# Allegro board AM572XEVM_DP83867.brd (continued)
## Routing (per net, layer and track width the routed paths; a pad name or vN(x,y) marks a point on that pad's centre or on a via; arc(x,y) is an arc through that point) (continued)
ETH1_TRD[1]N: length 43.3
  TOP w0.102: v3(105.76,71.06) 105.76,71.32 105.83,71.4 105.83,73.79 105.76,73.87 U49.6 105.79,74.31 105.79,75.09 U49.5 105.76,75.5 105.69,75.56 v1(105.69,75.84)
  TOP w0.12: v3(105.76,71.06) 105.76,70.29 U15.5
  INT_L3 w0.094: P5.5 98.32,94.16 98.12,93.96 98.12,92.16 97.48,91.52 94.76,91.52 93.78,90.54 93.78,88.05 95.48,86.36 106.73,86.36 108.57,84.52 108.57,79.81 105.81,77.05 105.81,76.33 105.69,76.21 v1(105.69,75.84)
  BOTTOM w0.102: v3(105.76,71.06) 105.77,71.05 C538.2
ETH1_TRD[1]P: length 43.2
  TOP w0.102: v1(106.32,75.84) 106.32,75.56 106.26,75.5 U49.4 106.22,75.09 106.22,74.31 U49.7 106.27,74.27 106.27,73.86 106.19,73.78 106.19,71.4 106.27,71.33 v3(106.27,71.06)
  TOP w0.12: v3(106.27,71.06) 106.27,70.3 U15.4
  INT_L3 w0.094: v1(106.32,75.84) 106.32,76.21 106.2,76.33 106.2,76.89 108.97,79.65 108.97,84.68 106.89,86.76 95.64,86.76 94.18,88.22 94.18,90.37 94.93,91.12 97.65,91.12 98.52,91.99 98.52,93.79 98.65,93.93 99.14,93.93 99.33,93.74 P5.11
  BOTTOM w0.102: v3(106.27,71.06) 106.27,71.05 C539.2
ETH1_TRD[2]N: length 44.1
  TOP w0.102: P5.10 101.35,92.98 101.35,94.03 101.55,94.23 101.76,94.23 102.16,93.83 102.16,92.04 101.63,91.52 96.75,91.52 95.73,90.5 95.73,88.45 97.64,86.54 106.53,86.54 107.65,85.42 107.65,78.33 106.43,77.11 105.13,77.11 104.33,76.32 104.33,75.65 104.26,75.58 U50.2 104.29,75.09 104.29,74.31 U50.9 104.26,73.85 104.34,73.76 104.34,73.62 104.33,73.61 104.33,71.39 104.26,71.32 v3(104.26,71.06)
  TOP w0.12: U15.8 104.26,70.29 v3(104.26,71.06)
  BOTTOM w0.102: v3(104.26,71.06) 104.24,71.04 C540.2
ETH1_TRD[2]P: length 44.2
  TOP w0.102: v3(104.77,71.06) 104.77,71.3 104.69,71.38 104.69,73.61 104.7,73.62 104.7,73.76 104.77,73.84 104.77,74.27 U50.10 104.72,74.31 104.72,75.09 U50.1 104.76,75.58 104.69,75.65 104.69,76.17 105.28,76.76 106.58,76.76 108,78.18 108,85.57 106.67,86.89 97.79,86.89 96.09,88.6 96.09,90.35 96.9,91.16 101.78,91.16 102.51,91.9 102.51,93.98 101.83,94.67 101.83,95 P5.3
  TOP w0.12: v3(104.77,71.06) 104.77,70.3 U15.7
  BOTTOM w0.102: v3(104.77,71.06) 104.75,71.04 C541.2
ETH1_TRD[3]N: length 44.1
  TOP w0.102: v3(102.76,71.06) 102.76,71.32 102.83,71.39 102.83,73.77 102.76,73.85 U50.6 102.79,74.31 102.79,75.09 U50.5 102.76,75.5 102.69,75.56 v1(102.69,75.84)
  TOP w0.12: U15.11 102.76,70.29 v3(102.76,71.06)
  INT_L3 w0.094: v1(102.69,75.84) 102.69,75.57 102.83,75.43 102.83,75.04 103.41,74.46 106.59,74.46 110.67,78.53 110.67,84.87 106.77,88.77 103.49,88.77 102.53,89.73 102.53,90.61 103.16,91.24 105.98,91.24 106.91,92.18 106.91,93.75 106.22,94.44 105.41,94.44 P5.2
  BOTTOM w0.102: v3(102.76,71.06) 102.77,71.05 C542.2
ETH1_TRD[3]P: length 44.1
  TOP w0.102: v1(103.33,75.84) 103.33,75.56 103.26,75.5 U50.4 103.26,75.13 103.26,75.02 103.23,74.98 103.23,74.31 U50.7 103.27,74.27 103.27,73.84 103.19,73.76 103.19,71.38 103.27,71.3 v3(103.27,71.06)
  TOP w0.12: U15.10 103.27,70.3 v3(103.27,71.06)
  INT_L3 w0.094: v1(103.33,75.84) 103.33,75.56 103.23,75.46 103.23,75.21 103.58,74.85 106.43,74.85 110.27,78.7 110.27,84.7 106.6,88.37 103.33,88.37 102.13,89.56 102.13,90.78 103,91.64 105.81,91.64 106.51,92.34 106.51,93.59 106.06,94.04 105.58,94.04 105.24,94.04 104.99,94.29 104.22,94.29 104.04,94.11 104.04,93.8 104.29,93.55 104.76,93.55 P5.8
  BOTTOM w0.102: C543.2 103.28,71.05 v3(103.27,71.06)
ETH1_XI: length 6.3
  TOP w0.12: Y6.2 99.6,67.26 99.8,67.46 99.8,68.38 100.09,68.67 v1(100.62,68.67) 100.75,68.54 U15.15
  BOTTOM w0.12: C232.2 100.61,68.68 v1(100.62,68.67) 101.38,68.67 R451.2
ETH1_XO: length 5
  TOP w0.12: Y6.1 98.17,71.04 v1(100.41,71.04) R480.1
  BOTTOM w0.12: v1(100.41,71.04) 100.41,69.8 100.2,69.6 C233.2
ETH_CLK_OUT: length 18.6
  INT_L3 w0.094: v1(87.63,69.95) 93.9,69.95 95.55,71.6 100.81,71.6 101.42,70.99 v1(101.42,70.48)
  BOTTOM w0.12: R451.1 v1(101.42,70.48) ; R477.1 v1(87.63,69.95)
ETH_RESETN: length 31.5
  TOP w0.12: v1(83.11,60.53) 83.39,60.81 U51.1 83.39,61.46 R476.2 ; U11.U3 v2(76.99,43.21)
  INT_L3 w0.094: v1(84.76,52.63) 84.45,52.32 v1(84.45,42.55)
  GND_L9 w0.094: v1(84.45,42.55) 83.01,41.1 81.94,41.1 81.31,41.73 78.74,41.73 78.51,41.96 76.7,41.96 76.56,42.11 76.56,42.77 v2(76.99,43.21)
  BOTTOM w0.12: v1(83.11,60.53) 83.11,54.28 v1(84.76,52.63)
EXP_SATA_RXN: length 69.8
  TOP w0.102: v3(73.15,88.27) 74.04,87.38 74.7,87.38 75.44,86.64 75.44,82.81 76.17,82.08 76.17,78.24 U31.22
  BOTTOM w0.102: P19.7 23.93,76.65 24.38,76.21 24.61,76.21 24.67,76.27 24.67,76.39 24.74,76.45 24.84,76.45 24.9,76.39 24.9,76.27 24.97,76.21 25.64,76.21 26.69,75.16 37,75.16 40.38,78.54 42.72,78.54 45.05,80.87 45.05,82.74 49.43,87.12 72.39,87.12 73.23,87.96 73.23,88.19 v3(73.15,88.27)
EXP_SATA_RXP: length 69.8
  TOP w0.102: U31.21 76.52,78.24 76.52,82.23 75.79,82.96 75.79,86.79 74.85,87.73 74.19,87.73 73.66,88.26 v3(73.66,88.27)
  BOTTOM w0.102: P19.8 25.5,75.85 26.54,74.8 37.15,74.8 40.53,78.18 42.86,78.18 45.41,80.73 45.41,82.59 49.58,86.77 72.54,86.77 73.58,87.81 73.58,88.19 v3(73.66,88.27)
EXP_SATA_TXN: length 91.5
  TOP w0.102: v3(71.88,88.27) 71.88,87.71 72.82,86.77 74.21,86.77 74.8,86.18 74.8,82.67 75.52,81.95 75.52,78.24 U31.23
  BOTTOM w0.102: P19.36 15.77,77.45 15.62,77.6 15.25,77.6 14.38,78.47 14.38,87.27 15.5,88.39 31.88,88.39 33.68,86.59 33.68,85.18 38.79,80.08 42.46,80.08 43.93,81.55 43.93,83.51 48.55,88.14 69.47,88.14 70.36,89.03 71.5,89.03 71.81,88.72 71.81,88.34 v3(71.88,88.27)
EXP_SATA_TXP: length 91.5
  TOP w0.102: v3(71.37,88.27) 71.53,88.11 71.53,87.56 72.67,86.41 74.07,86.41 74.45,86.03 74.45,82.52 75.17,81.81 75.17,78.24 U31.24
  BOTTOM w0.102: P19.35 15.77,78.25 15.62,78.11 15.24,78.11 14.73,78.61 14.73,78.87 14.8,78.94 15.05,78.94 15.11,79.01 15.11,79.1 15.05,79.17 14.8,79.17 14.73,79.23 14.73,79.33 14.8,79.4 15.05,79.4 15.11,79.46 15.11,79.56 15.05,79.62 14.8,79.62 14.73,79.69 14.73,79.79 14.8,79.85 15.05,79.85 15.11,79.92 15.11,80.02 15.05,80.08 14.8,80.08 14.73,80.15 14.73,87.12 15.65,88.04 31.73,88.04 33.33,86.44 33.33,85.04 38.64,79.72 42.6,79.72 44.29,81.41 44.29,83.37 48.7,87.78 69.62,87.78 70.51,88.67 71.35,88.67 71.45,88.57 71.45,88.34 v3(71.37,88.27)
EXT_WAKE: length 110.8
  TOP w0.12: U11.AC16 v2(65.79,48.01) ; U6.7 85.34,83.44 85.47,83.57 86.49,83.57 87.5,82.55 87.5,80.64 87.41,80.55 R33.2 v1(87,79.88)
  SIG_L5 w0.094: v1(87,79.88) 87,76.15 84.96,74.12 84.96,61.42 85.62,60.76 85.62,58.6 84.61,57.58 81.46,57.58 v1(81.15,57.28)
  SIG_L8 w0.094: v1(81.15,57.28) 79.88,56.01 79.88,50.16 78.87,49.16 66.44,49.16 66.23,48.95 66.23,48.45 v2(65.79,48.01)
  BOTTOM w0.12: v1(81.15,57.28) 81.92,56.52 81.92,54.36 85.22,51.05 104.39,51.05 105.41,50.04 105.41,46.86 106.3,45.97 107.31,45.97 107.82,45.47 107.82,40.51 108.27,40.07 109.16,40.07 112.88,36.34 P18.35 ; R49.1 64.59,53.06 64.59,49.44 64.82,49.21 65.15,49.21 65.39,48.97 65.39,48.64 65.79,48.24 v2(65.79,48.01)
GPIO2_2: length 62.8
  TOP w0.12: U11.P4 v2(76.19,40.01)
  SIG_L5 w0.094: v2(76.19,40.01) 76.19,40.12 76.68,40.61 77.15,40.61 77.43,40.89 78,40.89 78.16,41.05 78.82,41.05 79.18,41.4 81.79,41.4 82.04,41.15 86.49,41.15 90.42,45.09 97.28,45.09 99.95,47.75 101.35,47.75 108.87,55.27 111.4,55.27 117.35,61.21 117.35,69.61 v1(116.71,70.25)
  BOTTOM w0.12: v1(116.71,70.25) 116.71,70.25 115.91,69.45 P16.46
GPIO2_3: length 67.6
  TOP w0.12: U11.R3 v2(76.99,41.61)
  SIG_L10 w0.094: v1(119.13,76.65) 118.69,77.09 117.98,77.09 117.12,76.22 117.12,74.57 116.36,73.82 116.36,73.31 116.08,73.03 115.32,73.03 114.3,72.01 114.3,59.69 111.6,56.99 106.62,56.99 98.4,48.77 92.33,48.77 91.82,48.26 90.81,48.26 84.69,42.14 81.89,42.14 81.66,41.91 78.01,41.91 77.94,41.98 77.42,41.98 77.04,41.61 v2(76.99,41.61)
  BOTTOM w0.12: P16.7 v1(119.13,76.65)
GPIO2_4: length 63.3
  TOP w0.12: U11.T2 v2(77.79,42.41)
  SIG_L10 w0.094: v2(77.79,42.41) 77.79,42.48 78.11,42.8 78.87,42.8 79.02,42.95 81.56,42.95 81.81,43.2 81.81,43.58 82.04,43.81 84.46,43.81 89.92,49.28 98.04,49.28 106.2,57.43 111.28,57.43 113.79,59.94 113.79,72.39 115.7,74.3 115.96,74.3 v1(116.71,75.05)
  BOTTOM w0.12: v1(116.71,75.05) 115.91,74.25 P16.40
GPIO2_5: length 63
  TOP w0.12: U11.U2 v2(77.79,43.21)
  SIG_L10 w0.094: v1(116.71,76.65) 113.28,73.22 113.28,61.37 111.3,59.38 107.16,59.38 98.58,50.8 90.42,50.8 84.45,44.83 81.15,44.83 80.39,44.07 79.26,44.07 78.77,43.58 78.25,43.58 77.88,43.21 v2(77.79,43.21)
  BOTTOM w0.12: v1(116.71,76.65) 116.71,76.65 115.91,75.85 P16.38
GPIO2_6: length 60
  TOP w0.12: U11.U1 v2(78.59,43.21)
  SIG_L10 w0.094: v2(78.59,43.21) 78.89,43.21 79.1,43.41 79.1,43.6 79.34,43.84 80.67,43.84 80.9,44.07 84.2,44.07 90.17,50.04 98.4,50.04 106.05,57.68 111.15,57.68 113.54,60.07 113.54,72.77 v1(115.82,75.05)
  BOTTOM w0.12: P16.39 v1(115.82,75.05)
GPIO2_8: length 67
  TOP w0.12: U11.R2 v2(77.79,41.61)
  SIG_L10 w0.094: v1(118.24,76.65) 117.35,75.76 117.35,73.55 116.57,72.77 115.44,72.77 114.55,71.88 114.55,59.63 110.93,56.01 106.02,56.01 98.53,48.51 92.46,48.51 91.95,48.01 91.06,48.01 84.31,41.25 82.13,41.25 81.78,41.61 81.77,41.61 81.75,41.62 77.8,41.62 v2(77.79,41.61)
  BOTTOM w0.12: P16.8 119.04,75.85 118.24,76.65 v1(118.24,76.65)
GPIO2_17: length 56.7
  TOP w0.12: U11.P3 v2(76.99,40.01)
  SIG_L8 w0.094: v1(116.71,68.65) 116.71,68.33 116.33,67.94 114.12,67.94 111.9,65.72 111.9,64.98 108.86,61.95 108.14,61.95 100.04,53.85 93.34,53.85 82.87,43.37 82.87,41.72 82.42,41.27 81.53,41.27 81.41,41.4 79.12,41.4 78.76,41.05 78.07,41.05 77.79,40.77 77.6,40.77 76.99,40.16 v2(76.99,40.01)
  BOTTOM w0.12: v1(116.71,68.65) 115.91,67.85 P16.48
GPIO2_19: length 59.7
  TOP w0.12: U11.T1 v2(78.59,42.41)
  SIG_L10 w0.094: v2(78.59,42.41) 78.85,42.14 81.57,42.14 81.89,42.46 81.89,42.71 82.11,42.93 84.07,42.93 89.66,48.51 91.69,48.51 92.2,49.02 98.17,49.02 106.36,57.21 111.44,57.21 114.05,59.82 114.05,72.14 115.36,73.45 v1(115.82,73.45)
  BOTTOM w0.12: P16.41 v1(115.82,73.45)
GPIO2_20: length 53.5
  TOP w0.12: U11.P2 v2(77.79,40.01)
  SIG_L8 w0.094: v1(115.82,67.05) 115.69,67.05 112.57,63.93 112.57,62.34 111.27,61.04 108.03,61.04 100.34,53.34 93.85,53.34 83.31,42.8 83.31,41.27 82.55,40.51 82.04,40.51 81.66,40.13 79.38,40.13 78.9,40.6 78.34,40.6 78.21,40.47 77.79,40.05 v2(77.79,40.01)
  BOTTOM w0.12: P16.49 v1(115.82,67.05)
GPIO2_23: length 54.9
  TOP w0.12: U11.N1 v2(78.59,39.21)
  SIG_L8 w0.094: v2(78.59,39.21) 78.78,39.01 82.7,39.01 91.19,47.5 96.29,47.5 108.59,59.79 111.28,59.79 113.54,62.05 113.54,63.44 115.12,65.02 115.95,65.02 116.2,65.28 116.2,65.53 116.53,65.85 118.72,65.85 v1(119.13,65.45)
  BOTTOM w0.12: P16.21 v1(119.13,65.45)
GPIO2_24: length 57.9
  TOP w0.12: U11.M5 v2(75.39,38.41)
  SIG_L8 w0.094: v1(115.82,68.65) 114.12,68.65 111.1,65.63 109.88,65.63 107.87,63.63 105.12,63.63 97.81,56.32 93.76,56.32 86.41,48.97 86.41,47.93 82.55,44.07 82.04,44.07 81.79,43.81 81.79,42.42 81.28,41.91 79.05,41.91 78.98,41.98 77.63,41.98 77.41,41.76 77.41,41.47 76.45,40.51 76.16,40.51 75.81,40.16 75.81,39.89 75.54,39.63 75.28,39.63 75.02,39.37 75.01,39.37 75.01,38.83 75.39,38.45 v2(75.39,38.41)
  BOTTOM w0.12: P16.47 v1(115.82,68.65)
GPIO2_25: length 59.3
  TOP w0.12: U11.M3 v2(76.99,38.41)
  SIG_L8 w0.094: v1(119.13,67.05) 118.72,67.45 116.55,67.45 116.31,67.22 116.31,66.78 116.08,66.55 115.57,66.55 112.79,63.77 112.79,62.25 111.25,60.71 108.13,60.71 96.7,49.28 90.3,49.28 83.57,42.55 83.57,41.15 82.7,40.28 82.13,40.28 81.73,39.88 79.25,39.88 78.74,40.38 78.43,40.38 78.21,40.16 78.21,39.89 77.94,39.62 77.6,39.62 77.36,39.39 77.36,38.78 v2(76.99,38.41)
  BOTTOM w0.12: P16.19 v1(119.13,67.05)
GPIO2_28: length 56.4
  TOP w0.12: U11.N2 v2(77.79,39.21)
  SIG_L8 w0.094: v1(118.24,67.05) 117.26,66.07 115.86,66.07 113.31,63.53 113.31,62.14 111.24,60.07 108.46,60.07 96.14,47.75 91.06,47.75 82.55,39.24 79.12,39.24 78.74,39.62 78.36,39.62 77.94,39.21 v2(77.79,39.21)
  BOTTOM w0.12: v1(118.24,67.05) 119.04,66.25 P16.20
GPIO2_31: length 62.2
  TOP w0.12: U11.AH7 v2(73.79,52.01)
  SIG_L8 w0.094: v2(73.79,52.01) 73.55,52.01 72.72,52.83 67.62,52.83 66.08,54.37 63.99,54.37 62.47,55.9 53.99,55.9 48.93,60.96 20.15,60.96 19.94,61.16 19.94,61.34 19.83,61.45 19.66,61.45 19.06,62.04 18.24,62.04 v1(18.03,62.25)
  BOTTOM w0.12: v1(18.03,62.25) P19.55
GPIO3_6: length 62.2
  TOP w0.12: U11.AG7 v2(73.79,51.21)
  SIG_L8 w0.094: v1(18.03,61.45) 18.22,61.64 18.9,61.64 19.98,60.56 48.76,60.56 53.82,55.5 62.3,55.5 63.83,53.98 65.91,53.98 67.45,52.43 72.56,52.43 v2(73.79,51.21)
  BOTTOM w0.12: P19.56 v1(18.03,61.45)
GPIO3_7: length 64.2
  TOP w0.12: U11.AH6 v2(74.59,52.01)
  SIG_L8 w0.094: v2(74.59,52.01) 74.57,52.02 74.57,52.36 73.21,53.72 69.02,53.72 67.09,55.64 63.86,55.64 62.85,56.66 54.7,56.66 49.24,62.12 21.95,62.12 19.83,64.25 18.12,64.25 18.03,64.34 v1(18.03,64.65)
  BOTTOM w0.12: P19.52 v1(18.03,64.65)
GPIO3_8: length 72.7
  TOP w0.12: U11.AH3 v2(76.99,52.01)
  SIG_L8 w0.094: v1(18.92,69.45) 18.92,69.22 18.8,69.09 18.63,69.09 18.51,69.21 18.51,69.89 19.54,70.92 30.56,70.92 35.92,65.56 49.61,65.56 56.63,58.53 63.77,58.53 64.02,58.28 68.85,58.28 71.12,56.01 75.06,56.01 77.04,54.03 77.04,52.05 v2(76.99,52.01)
  BOTTOM w0.102: v1(18.92,69.45) 18.12,70.25 P19.45
GPIO3_9: length 66.6
  TOP w0.12: U11.AH5 v2(75.39,52.01)
  SIG_L8 w0.094: v1(18.03,67.85) 18.03,67.54 18.13,67.45 20.11,67.45 24.42,63.14 49.7,63.14 55.43,57.4 63.19,57.4 64.06,56.53 67.73,56.53 69.63,54.63 73.44,54.63 75.39,52.69 v2(75.39,52.01)
  BOTTOM w0.102: v1(18.03,67.85) P19.48
GPIO3_10: length 64.2
  TOP w0.12: U11.AG6 v2(74.59,51.21)
  SIG_L8 w0.094: v2(74.59,51.21) 74.17,51.62 74.17,52.2 73.04,53.32 68.85,53.32 66.93,55.24 63.7,55.24 62.68,56.26 54.53,56.26 49.07,61.72 21.79,61.72 19.66,63.85 v1(18.03,63.85)
  BOTTOM w0.12: P19.53 v1(18.03,63.85)
GPIO3_11: length 66.9
  TOP w0.12: U11.AH4 v2(76.19,52.01)
  SIG_L8 w0.094: v1(20.45,70.23) 20.88,69.8 30.15,69.8 35.31,64.64 45.57,64.64 46.61,63.6 50.11,63.6 55.95,57.77 63.21,57.77 63.46,57.51 67.84,57.51 70.23,55.12 73.66,55.12 76.19,52.59 v2(76.19,52.01)
  BOTTOM w0.102: P19.14 21.27,71.05 v1(20.45,70.23)
GPIO3_12: length 67
  TOP w0.12: U11.AG4 v2(76.19,51.21)
  SIG_L8 w0.094: v1(21.34,70.25) 21.39,70.2 21.74,70.2 21.82,70.28 21.82,70.4 21.9,70.48 22.02,70.48 22.1,70.4 22.1,70.28 22.19,70.2 22.3,70.2 22.39,70.28 22.39,70.4 22.47,70.48 22.58,70.48 22.67,70.4 22.67,70.28 22.75,70.2 30.31,70.2 35.47,65.04 45.73,65.04 46.77,64 50.28,64 56.11,58.17 63.37,58.17 63.63,57.91 68,57.91 70.4,55.52 73.83,55.52 76.58,52.76 76.58,51.6 v2(76.19,51.21)
  BOTTOM w0.102: P19.15 v1(21.34,70.25)
GPIO3_14: length 72.8
  TOP w0.12: U11.AG3 v2(76.99,51.21)
  SIG_L8 w0.094: v2(76.99,51.21) 77.43,51.65 77.43,54.19 75.22,56.41 71.29,56.41 69.01,58.68 64.19,58.68 63.94,58.93 56.8,58.93 49.77,65.96 36.08,65.96 30.72,71.32 19.37,71.32 18.11,70.05 18.11,69.53 v1(18.03,69.45)
  BOTTOM w0.102: v1(18.03,69.45) P19.46
GPIO3_15: length 66.5
  TOP w0.12: U11.AG5 v2(75.39,51.21)
  SIG_L8 w0.094: v1(18.03,67.05) 19.94,67.05 24.26,62.74 49.53,62.74 55.26,57.01 63.03,57.01 63.9,56.13 67.56,56.13 69.47,54.23 73.28,54.23 74.99,52.52 74.99,51.6 v2(75.39,51.21)
  BOTTOM w0.102: v1(18.03,67.05) P19.49
GPIO3_16: length 78.7
  TOP w0.12: U11.AF2 v2(77.79,50.41)
  SIG_L8 w0.094: v1(18.03,72.65) 18.2,72.82 18.2,73.12 18.75,73.68 22.39,73.68 23.86,72.21 32.01,72.21 35.8,68.42 36.76,68.42 38.4,66.78 50.6,66.78 52.2,65.18 53.65,65.18 54.86,63.97 54.86,62.59 55.85,61.59 63.81,61.59 66.08,59.33 70.52,59.33 72.56,57.29 76.75,57.29 79.38,54.67 79.38,50.67 78.74,50.04 78.15,50.04 v2(77.79,50.41)
  BOTTOM w0.102: v1(18.03,72.65) P19.42
GPIO3_18: length 78.6
  TOP w0.12: U11.AF3 v2(76.99,50.41)
  SIG_L8 w0.094: v1(18.92,72.64) 18.8,72.64 18.6,72.84 18.6,72.96 18.92,73.28 22.23,73.28 23.69,71.81 31.84,71.81 35.64,68.02 36.6,68.02 38.24,66.38 50.43,66.38 52.03,64.78 53.48,64.78 54.46,63.8 54.46,62.43 55.69,61.2 63.64,61.2 65.91,58.93 70.36,58.93 72.39,56.9 76.58,56.9 78.98,54.5 78.98,51.04 78.74,50.8 77.39,50.8 v2(76.99,50.41)
  BOTTOM w0.102: v1(18.92,72.64) 18.13,71.85 P19.43
GPIO3_20: length 74.2
  TOP w0.12: U11.AF1 v2(78.59,50.41)
  SIG_L5 w0.094: v1(20.45,72.64) 20.86,73.05 22.25,73.05 25.2,70.1 49.48,70.1 52.45,67.13 52.45,63.56 57.44,58.56 71.48,58.56 73.84,56.21 73.84,55.7 74.94,54.6 75.83,54.6 78.14,52.29 78.14,52.15 78.14,52.15 78.14,50.85 v2(78.59,50.41)
  BOTTOM w0.102: v1(20.45,72.64) 21.25,73.45 P19.11
GPIO3_23: length 81.7
  TOP w0.12: U11.AE1 v2(78.59,49.61)
  SIG_L5 w0.094: v1(18.92,74.25) 18.92,74.46 19.07,74.6 22.3,74.6 22.51,74.39 22.51,74.28 22.24,74.01 22.24,73.89 22.33,73.81 22.44,73.81 22.71,74.08 22.82,74.08 22.91,73.99 22.91,73.88 22.64,73.61 22.64,73.5 22.73,73.41 22.84,73.41 23.11,73.68 23.22,73.68 23.64,73.26 36.21,73.26 37.23,72.25 51.12,72.25 55.81,67.56 55.81,63.11 57.7,61.21 65.15,61.21 67.28,59.09 74.59,59.09 75.31,58.36 75.31,57.99 78.99,54.31 78.99,50.01 v2(78.59,49.61)
  BOTTOM w0.102: P19.39 18.42,75.05 18.92,74.55 v1(18.92,74.25)
GPIO3_24: length 74.2
  TOP w0.12: U11.AE2 v2(77.79,49.61)
  SIG_L5 w0.094: v2(77.79,49.61) 77.67,49.61 77.34,49.93 77.34,52.52 75.66,54.2 74.78,54.2 73.44,55.53 73.44,56.04 71.32,58.17 57.28,58.17 52.05,63.39 52.05,66.97 49.31,69.71 25.04,69.71 23.52,71.22 23.34,71.22 23.13,71.44 23.13,71.62 22.96,71.78 22.84,71.78 22.51,71.45 22.4,71.45 22.32,71.54 22.32,71.65 22.64,71.98 22.64,72.1 22.56,72.18 22.44,72.18 22.12,71.85 22,71.85 21.92,71.94 21.92,72.05 22.24,72.38 22.24,72.5 22.09,72.65 v1(21.34,72.65)
  BOTTOM w0.102: v1(21.34,72.65) P19.12
GPIO3_26: length 81.7
  TOP w0.12: U11.AD2 v2(77.79,48.81)
  SIG_L5 w0.094: v2(77.79,48.81) 78.19,49.21 78.75,49.21 79.39,49.85 79.39,54.48 75.71,58.16 75.71,58.53 74.75,59.49 67.44,59.49 65.32,61.61 57.87,61.61 56.21,63.27 56.21,67.72 51.29,72.64 37.39,72.64 36.38,73.66 23.8,73.66 22.7,74.77 22.7,74.77 22.46,75 19.23,75 18.9,75 18.67,74.77 18.67,74.77 18.15,74.25 v1(18.03,74.25)
  BOTTOM w0.102: v1(18.03,74.25) P19.40
GPIO3_28: length 44.6
  TOP w0.12: U11.E1 v2(78.59,32.81)
  SIG_L5 w0.094: v1(119.13,31.54) 118.66,32 116.59,32 116.22,31.64 116.22,31.26 116.08,31.11 114.68,31.11 114.05,31.75 99.82,31.75 99.59,31.98 90.15,31.98 89.54,31.37 83.82,31.37 82.38,32.81 v2(78.59,32.81)
  BOTTOM w0.12: P18.11 v1(119.13,31.54)
GPIO3_29: length 50.8
  TOP w0.12: v1(108.37,53.51) 108.67,53.81 U44.1 108.64,54.44 R437.2 ; U11.G2 v2(77.79,34.41)
  INT_L3 w0.094: v1(96.7,35.92) 96.7,52.53 97.68,53.51 v1(108.37,53.51)
  SIG_L5 w0.094: v1(96.7,35.92) 96.47,35.69 80.14,35.69 79.23,34.78 78.43,34.78 78.05,34.41 v2(77.79,34.41)
GPIO3_30: length 52.1
  TOP w0.12: U11.H7 v2(73.79,35.21)
  SIG_L5 w0.094: v2(73.79,35.21) 73.79,35.47 74.21,35.89 74.21,36.16 74.48,36.43 74.74,36.43 75.01,36.69 75.01,36.96 75.28,37.23 75.54,37.23 75.81,37.49 75.81,37.76 76.08,38.03 76.34,38.03 76.61,38.29 76.61,38.56 76.88,38.83 77.14,38.83 77.41,39.09 77.41,39.36 77.63,39.58 77.9,39.58 78.21,39.89 78.21,40.16 78.43,40.38 78.74,40.38 78.89,40.23 78.89,40.23 79.12,40.01 81.85,40.01 82.13,40.28 97.68,40.28 98.23,40.83 99.5,40.83 99.82,41.15 106.05,41.15 106.32,40.87 112.18,40.87 v1(116.71,36.34)
  BOTTOM w0.12: v1(116.71,36.34) 115.91,35.54 P18.36
GPIO4_7: length 40.1
  TOP w0.12: U11.C1 v2(78.59,31.21)
  SIG_L5 w0.094: v2(78.59,31.21) 78.78,31.21 79.38,30.61 99.44,30.61 99.82,30.99 113.28,30.99 114.33,29.94 v1(115.82,29.94)
  BOTTOM w0.12: P18.43 v1(115.82,29.94)
GPIO4_8: length 45.1
  TOP w0.12: U11.E4 v2(76.19,32.81)
  SIG_L5 w0.094: v2(76.19,32.81) 76.58,33.2 76.58,33.78 77.63,34.83 77.94,34.83 78.21,35.09 78.21,35.36 78.43,35.58 78.84,35.58 79.2,35.94 95.86,35.94 96.37,36.45 98.58,36.45 99.09,35.94 106.81,35.94 109.61,33.14 v1(115.82,33.14)
  BOTTOM w0.12: P18.39 v1(115.82,33.14)
GPIO4_9: length 50.6
  TOP w0.12: U11.F5 v2(75.39,33.61)
  SIG_L5 w0.094: v2(75.39,33.61) 75.39,33.61 75.81,34.03 75.81,34.56 76.03,34.78 76.3,34.78 76.61,35.09 76.61,35.36 76.83,35.58 77.1,35.58 77.41,35.89 77.41,36.16 77.63,36.38 77.9,36.38 78.21,36.69 78.21,36.96 78.43,37.18 80.67,37.18 80.77,37.08 83.95,37.08 85.22,38.35 100.33,38.35 101.35,39.37 106.29,39.37 111.62,34.04 116.33,34.04 116.71,34.42 v1(116.71,34.74)
  BOTTOM w0.12: P18.38 115.91,33.94 116.71,34.74 v1(116.71,34.74)
GPIO4_10: length 53.7
  TOP w0.12: U11.E6 v2(74.59,32.81)
  SIG_L5 w0.094: v2(74.59,32.81) 74.59,32.81 75.01,33.23 75.01,34.56 75.28,34.83 75.54,34.83 75.76,35.05 75.76,35.32 76.08,35.63 76.34,35.63 76.56,35.85 76.56,36.12 77.68,37.23 77.94,37.23 78.16,37.45 78.16,37.72 78.48,38.03 84.38,38.03 84.96,38.61 98.81,38.61 99.82,39.62 106.43,39.62 111.76,34.29 116.08,34.29 116.22,34.43 116.22,34.94 116.46,35.18 118.69,35.18 v1(119.13,34.74)
  BOTTOM w0.12: P18.7 v1(119.13,34.74)
GPIO4_17: length 91.7
  TOP w0.12: U11.A12 v2(68.99,29.61)
  SIG_L8 w0.094: v2(68.99,29.61) 68.99,29.31 70.1,28.19 78.99,28.19 81.41,30.61 82.68,30.61 83.44,31.37 83.44,32.26 84.45,33.27 84.45,33.91 88.52,37.97 96.01,37.97 97.54,39.5 99.44,39.5 100.84,40.89 105.16,40.89 120.9,56.64 120.9,78.61 119.67,79.85 v1(119.13,79.85)
  BOTTOM w0.12: P16.3 v1(119.13,79.85)
GPIO5_4: length 72
  TOP w0.12: U11.G13 v2(68.99,34.41)
  INT_L3 w0.094: v2(68.99,34.41) 68.58,34 68.58,33.4 68.36,33.18 67.98,33.18 67.56,32.77 67.56,29.21 66.29,27.94 60.58,27.94 59.94,27.3 59.94,25.91 59.06,25.02 55.69,25.02 52.7,22.04 52.7,21.08 48.51,16.89 32.39,16.89 30.99,18.29 30.99,24.26 v1(29.21,26.04)
  BOTTOM w0.12: v1(29.21,26.04) 27.05,26.04 25.92,27.17 21.71,27.17 21.71,27.18 18.47,27.18 18.03,26.74 P17.47
GPIO5_5: length 69.9
  TOP w0.12: U11.J11 v2(70.59,36.01)
  INT_L3 w0.094: v1(31.5,26.04) 33.4,24.13 33.4,18.54 34.54,17.4 48.26,17.4 52.21,21.35 52.21,22.31 55.72,25.81 57.69,25.81 58.57,26.7 58.57,27.58 59.44,28.45 65.79,28.45 66.17,28.83 66.17,29.59 67.06,30.48 67.06,33.02 67.56,33.53 67.56,36.83 67.94,37.21 69.98,37.21 70.23,36.96 70.23,36.36 v2(70.59,36.01)
  BOTTOM w0.12: v1(31.5,26.04) 29.88,26.04 29.37,25.53 27.05,25.53 25.84,26.74 P17.17
GPIO5_6: length 101.3
  TOP w0.12: U11.E12 v2(69.79,32.81)
  SIG_L5 w0.094: v1(29.21,28.07) 18.8,28.07 17.27,26.54 17.27,18.54 18.16,17.65 21.59,17.65 25.78,13.46 35.69,13.46 36.58,14.35 49.78,14.35 54.61,19.18 54.61,23.62 55.12,24.13 60.33,24.13 62.77,26.57 63.14,26.57 63.34,26.78 63.34,27.02 63.63,27.3 66.04,27.3 67.69,28.96 67.69,31.37 67.9,31.58 68.3,31.58 68.58,31.87 68.58,32.26 68.7,32.38 69.36,32.38 v2(69.79,32.81)
  BOTTOM w0.12: v1(29.21,28.07) 27.05,28.07 26.36,28.76 18.44,28.76 18.03,28.34 P17.45
GPIO5_7: length 98.6
  TOP w0.12: U11.F13 v2(68.99,33.61)
  SIG_L5 w0.094: v2(68.99,33.61) 68.99,33.43 68.58,33.02 68.58,32.64 68.33,32.38 68.03,32.38 67.47,31.82 67.47,29.12 65.91,27.56 63.12,27.56 62.45,26.89 62.45,26.64 60.2,24.38 54.99,24.38 54.36,23.75 54.36,19.27 49.69,14.61 36.45,14.61 35.56,13.72 25.91,13.72 21.72,17.91 18.29,17.91 17.53,18.67 17.53,26.42 18.67,27.56 30.99,27.56 v1(31.5,28.07)
  BOTTOM w0.12: v1(31.5,28.07) 29.88,28.07 29.37,27.56 27.05,27.56 26.27,28.34 P17.15
GPIO5_8: length 69.4
  TOP w0.12: v1(64.01,23.5) 64.01,26.04 v1(63.88,26.16) ; U11.C12 v2(69.79,31.21)
  SIG_L5 w0.094: v2(69.79,31.21) 69.36,30.78 69.36,29.35 65.8,25.78 64.26,25.78 v1(63.88,26.16)
  SIG_L10 w0.094: v1(18.03,20.34) 18.64,20.95 19.23,20.95 19.23,20.96 21.84,20.96 24.64,18.16 30.23,18.16 32.39,16 49.66,16 52.83,19.18 52.83,23.88 54.1,25.15 57.66,25.15 58.42,24.38 63.12,24.38 v1(64.01,23.5)
  BOTTOM w0.12: P17.55 v1(18.03,20.34)
GPIO5_9: length 65.3
  TOP w0.12: U11.D12 v2(69.79,32.01) ; v1(62.99,26.16) 62.87,26.04 v1(62.87,23.5)
  SIG_L5 w0.094: v2(69.79,32.01) 68.58,30.8 68.58,29.46 65.68,26.56 63.65,26.56 63.25,26.16 v1(62.99,26.16)
  SIG_L10 w0.094: v1(21.34,20.34) 22.08,20.34 25.15,17.27 30.73,17.27 32.26,15.75 49.78,15.75 53.09,19.05 53.09,23.75 54.23,24.89 57.53,24.89 58.29,24.13 62.23,24.13 v1(62.87,23.5)
  BOTTOM w0.12: P17.25 v1(21.34,20.34)
GPIO5_10: length 92.7
  TOP w0.12: U11.B12 v2(69.79,30.41)
  SIG_L8 w0.094: v2(69.79,30.41) 71.24,28.96 78.61,28.96 80.98,31.32 80.98,32.59 81.28,32.89 82.93,32.89 83.69,33.66 83.69,34.29 88.14,38.73 95.25,38.73 97.35,40.83 98.87,40.83 99.7,41.66 99.7,42.42 103.38,46.1 105.27,46.1 105.44,46.27 106.12,46.27 106.39,46.54 107.03,46.54 107.21,46.54 111.4,50.73 113.84,50.73 120.14,57.03 120.14,78.23 119.51,78.87 117.7,78.87 v1(116.71,79.85)
  BOTTOM w0.12: v1(116.71,79.85) 115.91,79.05 P16.34
GPIO5_11: length 91.3
  TOP w0.12: U11.A11 v2(69.79,29.61)
  SIG_L8 w0.094: v1(118.24,79.85) 118.24,79.5 118.62,79.12 119.63,79.12 120.4,78.36 120.4,56.9 104.9,41.4 100.58,41.4 99.19,40.01 97.03,40.01 95.5,38.48 88.27,38.48 83.95,34.16 83.95,33.53 82.93,32.51 82.93,31.62 82.42,31.11 81.15,31.11 78.74,28.7 70.69,28.7 v2(69.79,29.61)
  BOTTOM w0.12: v1(118.24,79.85) 119.04,79.05 P16.4
GPIO5_12: length 95.3
  TOP w0.12: U11.B13 v2(68.99,30.41)
  SIG_L8 w0.094: v2(68.99,30.41) 69.36,30.03 69.36,29.44 70.36,28.45 78.87,28.45 81.28,30.86 82.55,30.86 83.19,31.5 83.19,32.38 84.2,33.4 84.2,34.04 88.39,38.23 95.76,38.23 97.28,39.75 99.31,39.75 100.71,41.15 105.03,41.15 120.65,56.77 120.65,78.49 119.76,79.38 118.87,79.38 118.72,79.52 118.72,80.03 118.49,80.26 116.23,80.26 v1(115.82,79.85)
  BOTTOM w0.12: P16.33 v1(115.82,79.85)
GPIO5_18: length 72.4
  TOP w0.12: U11.V2 v2(77.79,44.01)
  INT_L3 w0.094: v1(98.17,52.07) 105.16,52.07 108.97,48.26 108.97,40.89 114.05,35.81 114.05,18.91 v1(115.82,17.14)
  SIG_L10 w0.094: v2(77.79,44.01) 77.79,44.31 78.14,44.66 78.14,44.86 78.43,45.16 80.34,45.16 81.53,46.35 84.96,46.35 90.17,51.56 97.66,51.56 v1(98.17,52.07)
  BOTTOM w0.12: P18.59 v1(115.82,17.14)
GPIO5_19: length 74.6
  TOP w0.12: U11.Y1 v2(78.59,45.61)
  INT_L3 w0.094: v1(119.13,17.14) 118.36,17.91 115.82,17.91 114.55,19.18 114.55,36.07 109.47,41.15 109.47,48.51 105.16,52.83 v1(98.17,52.83)
  SIG_L10 w0.094: v1(98.17,52.83) 97.66,52.32 90.42,52.32 84.96,46.86 81.53,46.86 80.28,45.61 v2(78.59,45.61)
  BOTTOM w0.12: P18.29 v1(119.13,17.14)
GPIO6_11: length 92.8
  TOP w0.12: U11.AB4 v2(76.19,47.21)
  SIG_L5 w0.094: v2(76.19,47.21) 76.58,47.6 76.58,49.78 75.82,50.55 75.82,52.32 75.5,52.64 74.87,52.64 69.98,57.53 57,57.53 47.22,67.31 45.42,67.31 44.3,68.42 32.36,68.42 26.67,62.74 26.67,50.55 24,47.88 24,40.61 v1(21.34,37.94)
  BOTTOM w0.12: P17.3 v1(21.34,37.94)
GPIO6_18: length 65.9
  TOP w0.12: U11.E17 v2(64.99,32.81)
  SIG_L10 w0.094: v1(61.72,23.5) 61.32,23.09 57.38,23.09 56.39,22.1 55.5,22.1 54.61,21.21 54.61,17.4 51.44,14.22 36.7,14.22 36.2,13.72 23.95,13.72 v1(18.92,18.74)
  BOTTOM w0.12: v2(64.99,32.81) 64.59,32.41 64.02,32.41 63.79,32.17 63.79,31.78 62.99,30.98 62.99,30.22 61.63,28.87 61.63,26.5 62.23,25.91 62.23,24 v1(61.72,23.5) ; v1(18.92,18.74) 18.12,17.94 P17.58
GPIO6_19: length 55.7
  TOP w0.12: v1(55.75,23.5) 55.75,26.29 v1(55.12,26.92) ; U11.B26 v2(57.79,30.41)
  INT_L3 w0.094: v1(55.12,26.92) 55.12,27.74 v2(57.79,30.41)
  SIG_L10 w0.094: v1(20.45,18.74) 25.22,13.97 36.07,13.97 36.58,14.48 51.31,14.48 54.38,17.55 54.38,22.5 54.89,23.01 55.27,23.01 v1(55.75,23.5)
  BOTTOM w0.12: v1(20.45,18.74) 21.25,17.94 P17.28
GPIO7_7: length 54.3
  TOP w0.12: U11.A25 v2(58.59,29.61)
  SIG_L10 w0.094: v1(18.03,23.54) 18.87,24.38 29.21,24.38 32.64,20.95 33.15,20.95 33.69,20.42 33.69,18.64 34.38,17.94 48.55,17.94 50.8,20.19 50.8,24.89 53.85,27.94 56.92,27.94 v2(58.59,29.61)
  BOTTOM w0.12: P17.51 v1(18.03,23.54)
GRSTZ: length 1.7
  TOP w0.12: 88.27,33.09 87.68,33.09 v1(87.38,33.4)
  BOTTOM w0.12: C246.1 87.5,33.53 v1(87.38,33.4)
HDMI1_DDC_SCL: length 92
  TOP w0.12: U11.C25 v2(58.59,31.21) ; U21.1 64.66,97.05 v1(65.02,97.41)
  INT_L3 w0.094: v1(65.02,97.41) 65.91,98.3 68.58,98.3 69.34,97.54 69.34,88.47 70.56,87.25 72.14,87.25 73.53,85.85 73.53,80.9 72.9,80.26 72.9,65.15 72.14,64.39 72.14,56.39 71.81,56.06 71.81,45.47 71.56,45.21 71.25,45.21 70.99,44.96 70.99,41.4 70.23,40.64 68.07,40.64 67.31,39.88 67.31,33.66 66.88,33.23 66.37,33.23 66.17,33.02 66.17,30.61 64.52,28.96 59.44,28.96 58.96,29.43 58.96,30.83 v2(58.59,31.21)
  BOTTOM w0.12: R246.2 v1(65.02,97.41)
HDMI1_DDC_SDA: length 74
  TOP w0.12: v1(64.39,97.41) 64.27,97.28 U21.2 ; U11.F17 v2(64.99,33.61)
  INT_L3 w0.094: v1(64.39,97.41) 65.02,96.77 65.66,96.77 68.48,93.95 68.48,87.91 70.31,86.08 70.31,80.39 68.96,79.04 68.96,67.06 67.06,65.15 67.06,58.55 68.61,56.99 68.61,42.16 68.47,42.03 67.94,42.03 66.9,40.99 66.13,40.99 65.41,40.26 65.41,35.05 65.18,34.83 64.88,34.83 64.61,34.56 64.61,33.98 v2(64.99,33.61)
  BOTTOM w0.12: R245.2 64.01,97.03 v1(64.39,97.41)
HDMI_5VOUT: length 5.7
  TOP w0.254: v1(61.34,97.66) 61.54,97.86 P11.18 ; v1(60.07,95.5) 60.27,95.3 U21.12
  INT_L3 w0.381: v1(61.34,97.66) 61.34,96.77 v1(60.07,95.5)
  BOTTOM w0.381: C265.1 v1(60.07,95.5)
HDMI_CEC_A: length 83.6
  TOP w0.12: v1(66.04,97.41) 66.04,96.27 65.48,95.7 U21.24 ; U11.B20 v2(62.59,30.41)
  INT_L3 w0.094: v2(62.59,30.41) 62.94,30.05 64.34,30.05 64.61,30.32 64.61,32.93 64.84,33.16 65.16,33.16 65.41,33.4 65.41,34.56 65.68,34.83 65.94,34.83 66.21,35.09 66.21,40.3 66.68,40.77 67.06,40.77 67.44,41.15 69.09,41.15 69.41,41.47 69.41,56.57 67.31,58.67 67.31,65.02 68.33,66.04 68.71,66.04 69.52,66.86 69.53,66.86 69.74,67.06 69.74,77.89 69.55,78.08 69.55,79.15 71.27,80.87 72.29,80.87 72.72,81.31 72.72,85.45 71.7,86.46 70.43,86.46 68.77,88.13 68.77,94.05 66.04,96.77 v1(66.04,97.41)
HDMI_CEC_B: length 11.5
  TOP w0.12: P11.13 59.04,100.31 v1(59.31,100.58) 60.2,101.47 62.61,101.47 63.25,100.84 63.25,97.79 62.66,97.21 U21.6
  BOTTOM w0.12: R237.2 v1(59.31,100.58)
HDMI_CT_HPD: length 87.7
  TOP w0.12: v1(66.8,94.74) 65.66,93.6 60.07,93.6 59.66,94.01 59.66,95.85 59.82,96.01 60.2,96.01 60.51,95.7 U21.11 ; U11.A24 v2(59.39,29.61)
  INT_L3 w0.094: v2(59.39,29.61) 59.74,29.96 59.74,30.45 60.11,30.83 62.74,30.83 63.76,31.85 63.76,34.52 64.03,34.78 64.37,34.78 64.56,34.97 64.56,40.43 65.36,41.23 66.75,41.23 67.82,42.29 67.82,57.4 66.8,58.42 66.8,65.66 68.2,67.06 68.2,78.74 69.44,79.98 69.44,86.33 68,87.78 68,93.55 v1(66.8,94.74)
  BOTTOM w0.12: v1(66.8,94.74) 66.8,96.14 66.45,96.49 R248.2
HDMI_HPD_A: length 88.3
  TOP w0.12: v1(66.8,97.41) 66.29,97.92 64.26,97.92 63.97,97.63 63.97,97.29 63.87,97.19 U21.3 ; U11.B21 v2(61.79,30.41)
  INT_L3 w0.094: v2(61.79,30.41) 62.98,29.21 64.39,29.21 65.41,30.23 65.41,32.96 65.63,33.18 65.95,33.18 66.17,33.4 66.17,34.54 66.42,34.8 66.8,34.8 67.06,35.05 67.06,40.01 67.94,40.89 69.6,40.89 69.93,41.23 69.94,41.23 70.16,41.45 70.16,56.2 67.56,58.8 67.56,64.9 68.45,65.79 69.6,65.79 70.61,66.8 70.61,77.45 70.61,77.45 70.61,79.83 71.27,80.49 72.59,80.49 73.15,81.05 73.15,85.62 71.97,86.81 70.49,86.81 69.06,88.24 69.06,94.13 66.8,96.39 v1(66.8,97.41)
HDMI_HPD_B: length 2.8
  TOP w0.12: P11.19 62.04,97.73 61.47,97.16 61.47,96.48 U21.9
HDMI_LS_OE: length 63.5
  TOP w0.12: U11.AG8 v2(73.79,49.61) ; v1(63.5,97.41) 63.46,97.37 U21.4
  INT_L3 w0.094: v1(63.5,97.41) 64.01,97.92 65.02,97.92 65.66,98.55 68.71,98.55 69.6,97.66 69.6,88.8 70.82,87.58 72.97,87.58 74.64,85.92 74.64,80.86 73.66,79.88 73.66,57.15 72.56,56.05 72.56,50.83 v2(73.79,49.61)
  BOTTOM w0.12: R247.2 62.99,96.9 v1(63.5,97.41)
HDMI_SCL_B: length 9.6
  TOP w0.12: P11.15 60.04,100.3 v1(60.33,100.58) 60.83,101.09 62.36,101.09 62.87,100.58 62.87,97.79 62.27,97.19 U21.7
  BOTTOM w0.12: R241.2 v1(60.33,100.58)
HDMI_SDA_B: length 8.1
  TOP w0.12: P11.16 60.54,100.16 60.96,100.58 v1(61.34,100.58) 62.23,100.58 62.48,100.33 62.48,97.79 61.86,97.17 U21.8
  BOTTOM w0.12: R242.1 v1(61.34,100.58)
HDMI_TX0+: length 7.5
  TOP w0.102: FL3.3 55.7,92.72 55.7,93.28 D16.1 55.7,94.19 55.7,95.96 56.36,96.61 56.36,97.65 56.04,97.97 P11.7
HDMI_TX0-: length 7.5
  TOP w0.102: FL3.2 56.06,92.72 56.06,93.28 D17.1 56.06,94.19 56.06,95.81 56.72,96.47 56.72,97.65 57.04,97.97 P11.9
HDMI_TX1+: length 8
  TOP w0.102: FL2.3 53.16,92.72 53.16,93.28 D14.1 53.16,94.19 53.16,95.83 53.6,96.27 53.85,96.27 54.86,97.28 54.86,97.65 54.54,97.97 P11.4
HDMI_TX1-: length 8
  TOP w0.102: FL2.2 53.52,92.72 53.52,93.28 D15.1 53.52,94.19 53.52,95.68 53.75,95.91 54,95.91 55.21,97.13 55.21,97.65 55.54,97.97 P11.6
HDMI_TX2+: length 9.1
  TOP w0.102: FL1.3 50.62,92.72 50.62,93.28 D12.1 50.62,94.19 50.62,95.96 51.82,97.16 53.09,97.16 53.36,97.43 53.36,97.65 53.04,97.97 P11.1
HDMI_TX2-: length 9.1
  TOP w0.102: P11.3 54.04,97.97 53.71,97.65 53.71,97.28 53.23,96.8 51.97,96.8 50.98,95.81 50.98,94.19 D13.1 50.98,93.28 50.98,92.72 FL1.2
HDMI_TXC+: length 7.3
  TOP w0.102: P11.10 57.54,97.97 57.86,97.65 57.86,96.44 58.24,96.06 58.24,94.19 D18.1 58.24,93.28 58.24,92.72 FL4.3
HDMI_TXC-: length 7.3
  TOP w0.102: P11.12 58.54,97.97 58.22,97.65 58.22,96.59 58.6,96.21 58.6,94.19 D19.1 58.6,93.28 58.6,92.72 FL4.2
HUB_XI: length 3.9
  TOP w0.12: R202.1 v1(87.5,27.18) 87.58,27.1 88.27,27.1
  BOTTOM w0.12: Y7.1 87.5,25.69 v1(87.5,27.18) R202.1
HUB_XO: length 11.9
  TOP w0.12: v1(85.09,27.18) R202.2 85.89,27.57 86,27.69 87.67,27.69 87.76,27.59 88.27,27.59
  BOTTOM w0.12: v1(85.09,27.18) 84.58,26.67 84.58,21.97 84.79,21.77 Y7.2 85.89,21.39 C240.1
I2C1_SCL: length 102.1
  TOP w0.12: U11.C20 v2(62.59,31.21) ; U5.L1 v2(62.99,77.61) ; v1(61.72,20.07) 61.14,20.07 60.89,19.82 U18.8 ; U4.1 70.02,17.49 v1(70.48,17.02) 70.99,16.51 72.01,16.51 72.26,16.76 R212.2
  INT_L3 w0.094: v2(62.99,77.61) 63.48,78.11 64.77,78.11 65.01,77.87 65.01,70.57 65.01,68.97 65.01,67.04 64.64,66.67 64.64,60.2 67.56,57.28 67.56,42.8 66.79,42.03 64,42.03 63.81,41.84 63.81,34.98 63.63,34.8 63.25,34.8 63.23,34.78 62.99,34.54 62.99,31.61 v2(62.59,31.21)
  SIG_L5 w0.094: v1(61.72,20.07) 67.44,20.07 v1(70.48,17.02)
  GND_L9 w0.094: v1(61.72,20.07) 61.78,20.01 61.92,20.01 62.48,20.57 62.48,28.91 62.21,29.19 62.21,30.84 62.57,31.21 v2(62.59,31.21)
  BOTTOM w0.12: v2(62.99,77.61) 62.99,77.62 R17.2 64.02,78.27 64.13,78.38 64.13,80.14 63.73,80.55 59.31,80.55 58.93,80.92 58.93,81.92 57.06,83.79 53.56,83.79 53.34,83.57 53.34,82.17 53.59,81.92 U8.6
I2C1_SDA: length 90.1
  TOP w0.12: R213.2 67.46,17.92 U4.6 68.67,17.36 68.37,17.06 v1(67.9,17.06) ; U18.9 60.17,20.93 v1(60.33,21.08) ; U5.L2 v2(62.99,76.81) ; U11.C21 v2(61.79,31.21)
  INT_L3 w0.094: v2(61.79,31.21) 62.21,31.63 62.21,34.56 62.45,34.8 62.74,34.8 62.99,35.05 62.99,42.55 63.25,42.8 66.8,42.8 67.31,43.31 67.31,57.15 64.39,60.07 64.39,66.8 64.16,67.03 64.16,76.17 63.91,76.42 63.37,76.42 v2(62.99,76.81)
  SIG_L5 w0.094: v1(60.33,21.08) 60.33,20.45 61.21,19.56 65.41,19.56 v1(67.9,17.06)
  GND_L9 w0.094: v2(61.79,31.21) 61.36,30.78 61.36,29.21 61.72,28.85 61.72,24.38 61.09,23.75 61.09,21.84 v1(60.33,21.08)
  BOTTOM w0.12: U8.5 56.01,83.19 56.36,83.54 56.92,83.54 58.68,81.78 58.68,79.8 60.67,77.81 R16.2 60.93,77.22 62.58,77.22 v2(62.99,76.81)
I2C3_SCL: length 75.8
  TOP w0.12: U6.6 84.84,82.42 85.09,82.17 v1(85.22,82.17) R392.2 ; U11.D14 v2(68.19,32.01)
  INT_L3 w0.094: v1(85.22,82.17) 85.22,81.71 84.96,81.46 83.06,81.46 82.25,80.64 82.25,65 89.66,57.58 89.66,39.75 v1(89.41,39.5)
  SIG_L8 w0.094: v2(68.19,32.01) 68.57,32.38 78.82,32.38 79.31,32.87 79.86,32.87 80.39,33.4 82.68,33.4 83.19,33.91 83.19,34.54 87.88,39.24 89.15,39.24 v1(89.41,39.5)
  BOTTOM w0.12: R393.1 v1(89.41,39.5)
I2C3_SDA: length 79.6
  TOP w0.12: U11.C14 v2(68.19,31.21) ; U6.5 v1(84.34,82.17) 84.34,81.51 R391.2
  INT_L3 w0.094: v1(84.34,82.17) 84.74,82.57 85.45,82.57 85.62,82.4 85.62,81.53 85.24,81.15 83.21,81.15 82.55,80.49 82.55,65.07 89.92,57.71 89.92,39.88 v1(90.3,39.5)
  SIG_L8 w0.094: v1(90.3,39.5) 89.79,38.99 88.01,38.99 83.44,34.42 83.44,33.78 82.8,33.15 80.65,33.15 80.04,32.54 80.04,32.28 79.86,32.11 79.86,31.35 79.29,30.78 68.61,30.78 v2(68.19,31.21)
  BOTTOM w0.12: R394.1 v1(90.3,39.5)
I2C4_SCL: length 73.2
  TOP w0.12: U11.J14 v2(68.19,36.01)
  INT_L3 w0.094: v2(68.19,36.01) 67.81,35.63 67.81,33.39 67.31,32.89 67.31,29.34 66.17,28.19 59.82,28.19 59.05,27.43 59.05,26.04 58.42,25.4 55.69,25.4 52.48,22.19 52.48,21.24 48.39,17.14 32.64,17.14 31.5,18.29 31.5,24.77 v1(29.21,27.05)
  BOTTOM w0.12: P17.46 18.02,27.54 18.42,27.94 26.16,27.94 27.05,27.05 v1(29.21,27.05)
I2C4_SDA: length 74.2
  TOP w0.12: U11.B14 67.39,30.41 67.39,29.9 67.46,29.82 67.46,26.65 69.22,24.89 v1(69.22,21.59)
  SIG_L10 w0.094: v1(69.22,21.59) 68.58,22.23 68.58,22.86 66.04,25.4 58.93,25.4 58.17,26.16 53.59,26.16 51.82,24.38 51.82,19.68 49.15,17.02 32.89,17.02 30.23,19.68 24.64,19.68 21.72,22.61 18.69,22.61 v1(18.03,21.94)
  BOTTOM w0.12: P17.53 v1(18.03,21.94)
I2C5_SCL: length 67.4
  TOP w0.12: U11.F12 v2(69.79,33.61)
  SIG_L8 w0.094: v1(78.23,23.24) 78.87,23.88 105.41,23.88 112.78,31.24 112.78,33.78 116.33,37.34 117.6,37.34 118.2,37.94 v1(118.24,37.94)
  GND_L9 w0.094: v2(69.79,33.61) 70.14,33.25 70.14,30.83 71.15,29.82 71.15,25.76 72.77,24.13 77.34,24.13 v1(78.23,23.24)
  BOTTOM w0.12: v1(118.24,37.94) 119.04,37.14 P18.4
I2C5_SDA: length 69
  TOP w0.12: U11.G12 v2(69.79,34.41)
  SIG_L8 w0.094: v1(119.13,37.94) 118.14,36.96 116.46,36.96 113.16,33.66 113.16,31.11 105.06,23.02 79.53,23.02 79.35,22.84 78,22.84 77.83,23.01 77.83,23.6 v1(78.23,24)
  GND_L9 w0.094: v1(78.23,24) 77.72,24.51 73.46,24.51 72.09,25.88 72.09,29.64 70.99,30.73 70.99,33.7 70.73,33.96 70.23,33.96 v2(69.79,34.41)
  BOTTOM w0.12: P18.3 v1(119.13,37.94)
LDO_VRTC: length 60.7
  TOP w0.254: U11.AB13 v2(68.19,47.21) ; v2(71.79,71.21) U5.A8
  INT_L3 w0.254: v1(69.09,64.77) 68.96,64.9 69.47,65.41 70.87,65.41 72.26,66.8 72.26,70.73 v2(71.79,71.21) 72.26,71.69 72.26,73.28 v2(71.88,73.66)
  SIG_L8 w0.254: v2(71.88,73.66) 71.5,73.28 69.98,73.28 69.22,72.52 66.04,72.52 65.9,72.38 59.07,72.38 v1(59.05,72.39)
  SIG_L10 w0.254: v1(59.05,72.39) 55.37,72.39 v1(55.12,72.14)
  BOTTOM w0.254: v2(71.88,73.66) 71.63,73.91 70.48,73.91 R433.2 ; R23.1 v1(69.09,64.77) 69.09,59.44 69.72,58.8 73.15,58.8 73.53,59.18 C110.1 74.84,59.85 J5.2 ; v1(55.12,72.14) 53.09,72.14 51.62,70.67 R56.1 ; R214.2 v1(59.05,72.39) ; v2(71.79,71.21) 72.13,70.87 74.42,70.87 74.84,71.28 C19.2
  BOTTOM w0.381: R20.2 58.83,76.45 58.38,76.01 58.38,72.77 58.76,72.39 v1(59.05,72.39)
LEDAA: length 1.4
  TOP w0.12: D4.2 66.39,1.78 R215.2
LEDAC: length 10.5
  TOP w0.12: D4.1 63.17,3.3 62.2,4.27 62.2,6.78 63.02,7.59 64.78,7.59 65.52,6.86 Q3.6
LEDBA: length 1.4
  TOP w0.12: D5.2 68.93,1.78 R216.2
LEDBC: length 5.2
  TOP w0.12: D5.1 67.94,3.96 67.72,4.19 64.64,4.19 64.02,4.81 Q3.3
LEDCA: length 1.4
  TOP w0.12: D6.2 71.47,1.78 R217.2
LEDCC: length 8.8
  TOP w0.12: Q4.6 75.4,6.82 74.37,7.85 72.85,7.85 71.83,6.83 71.83,5.38 70.48,4.04 D6.1
LEDDA: length 1.4
  TOP w0.12: R218.2 74.01,1.78 D7.2
LEDDC: length 2.7
  TOP w0.12: D7.1 73.03,3.89 74.15,5.02 Q4.3
LEFT_IN: length 11.3
  BOTTOM w0.12: R235.1 C255.2 49.37,9.84 P9.2 47.12,7.18 D10.2
LEFT_OUT: length 11.9
  BOTTOM w0.12: R226.1 37.05,12.79 C250.2 36.96,9.82 P8.2 34.32,7.18 D8.2
MCASP2_ACLKR: length 76.3
  TOP w0.12: U11.E15 v2(66.59,32.81)
  SIG_L5 w0.094: v2(66.59,32.81) 66.59,32.8 66.17,32.38 65.53,32.38 65.41,32.26 65.41,29.84 64.13,28.57 62.48,28.57 61.98,28.07 60.07,28.07 59.05,27.05 59.05,26.29 58.17,25.4 54.48,25.4 53.34,24.26 53.34,19.81 49.15,15.62 32.13,15.62 30.99,16.76 30.99,24.77 32,25.78 32,28.19 31.62,28.57 29.72,28.57 v1(29.21,29.08)
  BOTTOM w0.12: P17.44 18.09,29.14 18.52,29.57 26.56,29.57 27.05,29.08 v1(29.21,29.08)
MCASP2_AXR0: length 72
  TOP w0.12: v1(66.68,21.59) 66.1,22.17 66.1,26.22 66.96,27.09 66.96,29.38 66.59,29.76 66.59,30.41 U11.B15
  SIG_L10 w0.094: v1(66.68,21.59) 66.04,22.23 66.04,22.86 64.01,24.89 58.67,24.89 57.91,25.65 53.85,25.65 52.32,24.13 52.32,19.43 49.4,16.51 32.64,16.51 29.97,19.18 24.38,19.18 22.1,21.46 21.08,21.46 20.85,21.7 20.85,22.11 20.6,22.35 19.34,22.35 v1(18.92,21.94)
  BOTTOM w0.12: v1(18.92,21.94) 18.92,21.94 18.12,21.14 P17.54
MCASP2_AXR1: length 67.8
  TOP w0.12: U11.A15 66.99,29.79 67.21,29.56 67.21,22.32 v1(67.94,21.59)
  SIG_L10 w0.094: v1(21.34,21.94) 22,21.94 24.51,19.43 30.1,19.43 32.77,16.76 49.28,16.76 52.07,19.56 52.07,24.26 53.72,25.91 58.04,25.91 58.8,25.15 65.02,25.15 67.31,22.86 67.31,22.23 v1(67.94,21.59)
  BOTTOM w0.12: P17.23 v1(21.34,21.94)
MCASP2_AXR2: length 64
  TOP w0.12: U11.C15 v2(66.59,31.21)
  INT_L3 w0.094: v1(20.45,26.74) 21.27,27.56 29.84,27.56 30.73,26.67 31.5,26.67 33.66,24.51 33.66,18.67 34.67,17.65 48.13,17.65 51.94,21.46 51.94,22.86 57.79,28.7 64.64,28.7 66.59,30.65 v2(66.59,31.21)
  BOTTOM w0.12: v1(20.45,26.74) 21.25,25.94 P17.18
MCASP2_AXR3: length 62.3
  TOP w0.12: v1(65.41,26.16) 66.13,26.89 66.13,29.95 U11.A16
  SIG_L10 w0.094: v1(20.45,23.54) 20.45,23.37 20.96,22.86 27.69,22.86 28.07,22.48 29.21,22.48 31.94,19.75 31.94,18.67 32.58,18.03 33.15,18.03 33.91,17.27 49.02,17.27 51.56,19.81 51.56,24.51 53.47,26.42 58.29,26.42 59.08,25.63 64.88,25.63 v1(65.41,26.16)
  BOTTOM w0.12: v1(20.45,23.54) 21.25,22.74 P17.22
MCASP2_AXR4: length 68
  TOP w0.12: U11.D15 v2(66.59,32.01)
  SIG_L5 w0.094: v2(66.59,32.01) 66.17,31.59 66.17,30.23 64.26,28.32 62.61,28.32 62.1,27.81 60.58,27.81 59.94,27.18 59.94,25.91 59.15,25.11 54.58,25.11 53.59,24.13 53.59,19.68 49.28,15.37 32,15.37 30.73,16.64 30.73,26.29 v1(31.5,27.05)
  BOTTOM w0.12: P17.16 26.05,27.54 27.05,26.54 29.37,26.54 29.88,27.05 v1(31.5,27.05)
MCASP2_AXR5: length 69.2
  TOP w0.12: U11.B16 65.79,30.41 65.79,29.75 65.67,29.63 65.49,29.63 65.24,29.38 65.24,26.76 64.9,26.42 64.9,22.1 v1(65.41,21.59)
  SIG_L10 w0.094: v1(20.45,21.94) 20.45,21.46 20.7,21.21 21.97,21.21 24.26,18.92 29.84,18.92 32.51,16.26 49.53,16.26 52.58,19.3 52.58,24 53.98,25.4 57.79,25.4 58.55,24.64 63.63,24.64 64.52,23.75 64.52,22.48 v1(65.41,21.59)
  BOTTOM w0.12: P17.24 21.25,21.14 20.45,21.94 v1(20.45,21.94)
MCASP2_AXR6: length 63.3
  TOP w0.12: U11.B17 64.99,30.41 64.99,29.82 63.48,28.32 59.94,28.32 58.96,27.34 58.96,23.97 v1(59.44,23.5)
  SIG_L10 w0.094: v1(20.45,20.34) 20.45,19.81 20.7,19.56 22.1,19.56 24.89,16.76 30.48,16.76 32,15.24 50.04,15.24 53.59,18.8 53.59,23.5 54.48,24.38 57.28,24.38 58.17,23.5 v1(59.44,23.5)
  BOTTOM w0.12: P17.26 21.25,19.54 v1(20.45,20.34)
MCASP2_AXR7: length 63.5
  TOP w0.12: U11.A17 65.28,29.9 65.28,29.77 63.45,27.94 61.47,27.94 60.74,27.21 60.74,23.91 v1(60.33,23.5)
  SIG_L10 w0.094: v1(18.92,20.34) 19.33,20.74 20.66,20.74 20.85,20.55 20.85,20.04 21.08,19.81 22.23,19.81 25.02,17.02 30.61,17.02 32.13,15.49 49.91,15.49 53.34,18.92 53.34,23.62 54.36,24.64 57.4,24.64 58.14,23.9 59.92,23.9 v1(60.33,23.5)
  BOTTOM w0.12: P17.56 18.12,19.54 v1(18.92,20.34)
MCASP2_CLKX: length 55
  TOP w0.12: U11.A19 v2(63.39,29.61)
  SIG_L10 w0.094: v2(63.39,29.61) 63.39,29.6 61.47,27.69 53.95,27.69 51.05,24.79 51.05,20.09 48.69,17.72 34.22,17.72 33.47,18.48 33.47,19.62 33.02,20.07 32.64,20.07 28.96,23.75 22.56,23.75 22.35,23.54 v1(21.34,23.54)
  BOTTOM w0.12: P17.21 v1(21.34,23.54)
MCASP2_FSR: length 59.8
  TOP w0.12: v1(57.4,23.5) 58.13,24.22 58.13,27.27 59.56,28.7 61.68,28.7 U11.A20
  SIG_L10 w0.094: v1(57.4,23.5) 56.77,24.13 54.61,24.13 53.85,23.37 53.85,18.67 50.16,14.99 26.16,14.99 21.84,19.3 18.59,19.3 v1(18.03,18.74)
  BOTTOM w0.12: P17.57 v1(18.03,18.74)
MCASP2_FSX: length 60.1
  TOP w0.12: U11.A18 v2(64.19,29.61)
  SIG_L10 w0.094: v1(18.92,23.54) 19.39,24 20.7,24 20.85,23.85 20.85,23.35 21.08,23.11 27.94,23.11 28.32,22.73 29.46,22.73 32.39,19.81 32.39,19.3 32.64,19.05 33.02,19.05 33.24,18.83 33.24,18.32 34.06,17.5 48.82,17.5 51.31,19.98 51.31,24.68 54.06,27.43 62.01,27.43 v2(64.19,29.61)
  BOTTOM w0.12: P17.52 18.12,22.74 v1(18.92,23.54)
MCASP7_AXR0: length 84.3
  TOP w0.12: U11.E14 v2(68.19,32.81)
  SIG_L5 w0.094: v1(119.13,78.25) 119.89,77.49 119.89,62.23 119,61.34 118.01,61.34 111.68,55.02 108.99,55.02 101.47,47.5 100.08,47.5 95.12,42.55 90.17,42.55 88.27,40.64 82.04,40.64 81.66,40.26 79.25,40.26 78.9,40.6 78.34,40.6 78.19,40.45 77.7,40.45 77.41,40.16 77.41,39.67 77.32,39.58 76.83,39.58 76.61,39.36 76.61,39.09 76.34,38.83 76.08,38.83 75.81,38.56 75.81,38.29 75.54,38.03 75.28,38.03 75.01,37.76 75.01,37.49 74.74,37.23 74.48,37.23 74.21,36.96 74.21,36.69 73.94,36.43 73.64,36.43 73.36,36.15 73.36,35.85 73.14,35.63 72.84,35.63 72.56,35.35 72.56,35.05 72.34,34.83 72.04,34.83 71.76,34.55 71.76,34.25 71.54,34.03 68.88,34.03 68.61,33.76 68.61,33.49 68.19,33.07 v2(68.19,32.81)
  BOTTOM w0.12: P16.5 v1(119.13,78.25)
MCASP7_AXR1: length 65.1
  TOP w0.12: U11.A13 v2(68.19,30.41)
  INT_L3 w0.094: v1(18.03,25.14) 20.44,22.73 29.34,22.73 30.48,21.59 30.48,18.29 32.13,16.64 48.64,16.64 52.96,20.95 52.96,21.84 55.75,24.64 59.44,24.64 60.71,25.91 60.71,27.05 61.34,27.69 66.42,27.69 67.83,29.1 67.83,30.05 v2(68.19,30.41)
  BOTTOM w0.12: P17.49 v1(18.03,25.14)
MCASP7_CLKX: length 74.8
  TOP w0.12: U11.G14 v2(68.19,34.41)
  SIG_L5 w0.094: v1(18.92,26.74) 19.63,26.04 21.21,26.04 22.35,24.89 22.35,18.41 25.4,15.37 30.1,15.37 30.86,14.61 32.13,14.61 32.64,15.11 49.4,15.11 53.85,19.56 53.85,24 54.74,24.89 59.44,24.89 60.71,26.16 60.71,27.06 61.2,27.56 62.23,27.56 62.74,28.07 65.41,28.07 66.17,28.83 66.17,29.46 67.03,30.33 67.03,33.25 v2(68.19,34.41)
  BOTTOM w0.12: P17.48 18.12,25.94 v1(18.92,26.74)
MCASP7_FSX: length 69.8
  TOP w0.12: U11.F14 v2(68.19,33.61)
  SIG_L5 w0.094: v2(68.19,33.61) 67.25,32.67 67.25,29.28 65.79,27.81 62.87,27.81 62.36,27.3 61.99,27.3 61.75,27.07 61.75,26.57 59.82,24.64 54.86,24.64 54.1,23.88 54.1,19.43 49.53,14.86 32.77,14.86 32.26,14.35 30.73,14.35 29.97,15.11 25.27,15.11 22.1,18.29 22.1,24.38 v1(21.34,25.14)
  BOTTOM w0.12: P17.19 v1(21.34,25.14)
MDIO_CLK: length 53.3
  TOP w0.12: v1(100.62,68.03) 100.62,68.04 U15.16 ; U11.V1 v2(78.59,44.01) ; v1(86.87,67.74) 87.05,67.74 87.05,67.74 U14.16
  INT_L3 w0.094: v1(100.62,68.03) 99.81,68.03 98.7,69.14 97.13,69.14 96.72,68.73 94.44,68.73 93.83,68.12 88.7,68.12 88.32,67.74 v1(86.87,67.74) 86.56,67.74 86.39,67.56 86.39,65.76 88.52,63.63 88.52,59.61 90.68,57.45 90.68,49.66 v1(91.44,48.9)
  SIG_L5 w0.094: v2(78.59,44.01) 79.82,44.01 81.41,45.59 88.14,45.59 v1(91.44,48.9)
MDIO_DATA: length 81.4
  TOP w0.12: v1(100.62,67.4) 100.76,67.54 U15.17 ; U14.17 87.26,67.24 87.12,67.11 v1(86.87,67.11) ; U11.U4 v2(76.19,43.21)
  INT_L3 w0.094: v1(112.09,63.75) 111.56,64.29 111.56,68.22 110.67,69.11 108.99,69.11 108.18,68.3 102.41,68.3 101.51,67.4 v1(100.62,67.4) 99.2,67.4 98.7,67.89 94.77,67.89 93.98,67.11 v1(86.87,67.11)
  SIG_L10 w0.094: v2(76.19,43.21) 76.19,43.32 75.83,43.67 75.83,44.15 76.14,44.45 76.33,44.45 76.54,44.66 76.54,44.85 76.84,45.16 77.13,45.16 77.43,45.46 77.43,45.75 78.44,46.76 78.73,46.76 79.15,47.18 79.15,47.39 80.4,48.64 83.97,48.64 90.03,54.69 101.25,54.69 106.6,60.04 110.74,60.04 112.09,61.39 v1(112.09,63.75)
  BOTTOM w0.12: R442.2 86.22,67.11 v1(86.87,67.11)
MMC1_CLK: length 42.9
  TOP w0.12: R269.1 v1(67.77,15.75) ; U11.W6 v2(74.59,44.81)
  INT_L3 w0.094: v1(67.77,15.75) 67.77,16.08 67.89,16.21 68.35,16.21 68.5,16.05 68.5,15.16 68.3,14.96 67.84,14.96 67.59,15.21 67.21,15.21 67.09,15.1 67.09,14.36 67.51,13.94 71.45,13.94 72.09,14.58 72.09,16.08 72.52,16.51 72.52,24.38 73.85,25.72 73.85,28.89 74.17,29.21 74.17,44.39 v2(74.59,44.81)
MMC1_CMD: length 42.9
  TOP w0.12: R267.1 v1(72.85,15.82) ; U11.Y6 v2(74.59,45.61)
  INT_L3 w0.094: v1(72.85,15.82) 72.85,17.22 73.68,18.05 73.68,18.64 73.91,18.87 74.25,18.87 74.35,18.96 74.35,19.26 74.25,19.35 73.84,19.35 73.68,19.52 73.68,19.75 73.87,19.94 74.47,19.94 74.55,20.02 74.55,20.14 74.47,20.22 73.87,20.22 73.79,20.3 73.79,21.23 73.87,21.31 74.47,21.31 74.55,21.4 74.55,21.51 74.47,21.6 73.87,21.6 73.79,21.68 73.79,21.79 73.87,21.88 74.47,21.88 74.55,21.96 74.55,22.08 74.47,22.16 73.87,22.16 73.79,22.24 73.79,22.36 73.87,22.44 74.47,22.44 74.55,22.52 74.55,22.64 74.47,22.72 73.87,22.72 73.79,22.81 73.79,22.92 73.87,23 74.47,23 74.55,23.09 74.55,23.2 74.47,23.29 73.87,23.29 73.79,23.37 73.79,23.49 73.87,23.57 74.47,23.57 74.55,23.65 74.55,23.77 74.47,23.85 73.87,23.85 73.79,23.93 73.79,24.05 73.87,24.13 74.47,24.13 74.55,24.22 74.55,24.33 74.47,24.41 73.87,24.41 73.79,24.5 73.79,24.77 74.74,25.72 74.74,28.89 74.96,29.12 74.96,45.23 v2(74.59,45.61)
MMC1_DAT0: length 42.8
  TOP w0.12: U11.AA6 v2(74.59,46.41) ; R270.1 v1(66.5,15.75)
  INT_L3 w0.094: v1(66.5,15.75) 66.5,16.26 66.85,16.61 68.58,16.61 68.86,16.33 68.86,14.78 69.37,14.27 71.25,14.27 71.73,14.76 71.73,16.31 72.14,16.71 72.14,24.89 72.96,25.72 72.96,28.13 73.41,28.58 73.41,45.76 73.63,45.98 73.92,45.98 74.35,46.41 v2(74.59,46.41)
MMC1_DAT1: length 42.9
  TOP w0.12: R271.1 v1(65.23,15.75) ; U11.Y4 v2(76.19,45.61)
  INT_L3 w0.094: v2(76.19,45.61) 75.81,45.23 75.81,29.07 75.63,28.89 75.63,25.72 74.88,24.97 74.88,18.57 73.48,17.17 73.48,15.42 71.68,13.61 67.36,13.61 v1(65.23,15.75)
MMC1_DAT2: length 42.9
  TOP w0.12: R266.1 v1(75.39,15.82) ; U11.AA5 v2(75.39,46.41)
  INT_L3 w0.094: v2(75.39,46.41) 75.81,45.98 77.21,45.98 77.36,45.83 77.36,25.8 76.45,24.89 76.45,24.42 76.54,24.34 76.88,24.34 76.96,24.26 76.96,24.14 76.88,24.06 76.54,24.06 76.45,23.98 76.45,23.86 76.54,23.78 76.88,23.78 76.96,23.69 76.96,23.58 76.88,23.49 76.54,23.49 76.45,23.41 76.45,23.3 76.54,23.21 76.88,23.21 76.96,23.13 76.96,23.01 76.88,22.93 76.54,22.93 76.45,22.85 76.45,22.73 76.54,22.65 76.88,22.65 76.96,22.57 76.96,22.45 76.88,22.37 76.54,22.37 76.45,22.28 76.45,22.17 76.54,22.08 76.88,22.08 76.96,22 76.96,21.89 76.88,21.8 76.54,21.8 76.45,21.72 76.45,21.6 76.54,21.52 76.88,21.52 76.96,21.44 76.96,21.32 76.88,21.24 76.54,21.24 76.45,21.16 76.45,21.04 76.54,20.96 76.88,20.96 76.96,20.87 76.96,20.76 76.88,20.68 76.54,20.68 76.45,20.59 76.45,20.48 76.54,20.39 76.88,20.39 76.96,20.31 76.96,20.19 76.88,20.11 76.54,20.11 76.45,20.03 76.45,19.91 76.54,19.83 76.88,19.83 76.96,19.75 76.96,19.63 76.88,19.55 76.54,19.55 76.45,19.46 76.45,19.23 76.61,19.08 76.84,19.08 76.91,19 76.91,18.82 76.84,18.75 76.58,18.75 76.45,18.62 76.45,16.89 v1(75.39,15.82)
MMC1_DAT3: length 42.9
  TOP w0.12: R268.1 v1(74.12,15.82) ; U11.Y3 v2(76.99,45.61)
  INT_L3 w0.094: v2(76.99,45.61) 76.97,45.61 76.58,45.21 76.58,29.08 76.52,29.02 76.52,25.72 75.18,24.38 75.18,23.96 75.27,23.88 75.61,23.88 75.69,23.79 75.69,23.68 75.61,23.59 75.27,23.59 75.18,23.51 75.18,23.4 75.27,23.31 75.61,23.31 75.69,23.23 75.69,23.11 75.61,23.03 75.27,23.03 75.18,22.95 75.18,22.83 75.27,22.75 75.61,22.75 75.69,22.67 75.69,22.55 75.61,22.47 75.27,22.47 75.18,22.38 75.18,22.27 75.27,22.19 75.61,22.19 75.69,22.1 75.69,21.99 75.61,21.9 75.27,21.9 75.18,21.82 75.18,21.7 75.27,21.62 75.61,21.62 75.69,21.54 75.69,21.42 75.61,21.34 75.27,21.34 75.18,21.26 75.18,21.14 75.27,21.06 75.61,21.06 75.69,20.97 75.69,20.86 75.61,20.78 75.27,20.78 75.18,20.69 75.18,20.58 75.27,20.49 75.61,20.49 75.69,20.41 75.69,20.29 75.61,20.21 75.27,20.21 75.18,20.13 75.18,20.01 75.27,19.93 75.61,19.93 75.69,19.85 75.69,19.73 75.61,19.65 75.27,19.65 75.18,19.57 75.18,19.45 75.27,19.37 75.61,19.37 75.69,19.28 75.69,19.17 75.61,19.08 75.27,19.08 75.18,19 75.18,18.88 75.27,18.8 75.61,18.8 75.69,18.72 75.69,18.6 75.61,18.52 75.27,18.52 75.18,18.44 75.18,18.32 75.27,18.24 75.61,18.24 75.69,18.16 75.69,18.04 75.61,17.96 75.27,17.96 75.18,17.87 75.18,17.68 75.29,17.58 75.62,17.58 75.72,17.48 75.72,17.27 75.62,17.17 75.23,17.17 75.16,17.09 75.16,16.6 74.96,16.4 74.69,16.4 v1(74.12,15.82)
